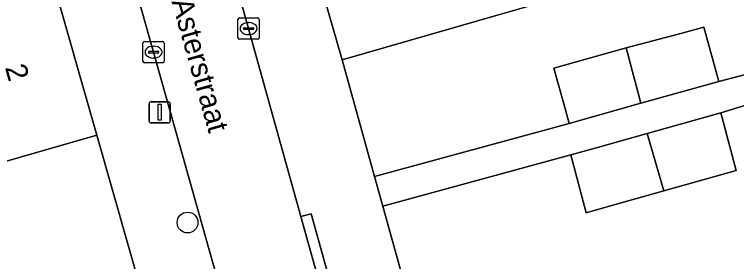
# Model space of a CAD drawing. Extents: x 161838 to 162344, y 381620 to 382160.
# Drawn here: x 162205.58 to 162239.49, y 381666.61 to 381678.21 of the extents above; entities that cross this region are included whole.
import ezdxf

# ---------------------------------------------------------------- set-up
doc = ezdxf.new("R2010")
doc.units = 0
for name, color, linetype in [('IMGEO_Boom', 7, 'Continuous'), ('IMGEO_Erf', 7, 'Continuous'), ('IMGEO_Kolk', 7, 'Continuous'), ('IMGEO_Lichtmast', 7, 'Continuous'), ('IMGEO_Muur', 7, 'Continuous'), ('IMGEO_Openbare_ruimte_label', 7, 'Continuous'), ('IMGEO_Pand', 7, 'Continuous'), ('IMGEO_Pand_nummerreeks', 7, 'Continuous'), ('IMGEO_Rijbaan_lokaal_open', 7, 'Continuous'), ('IMGEO_Voetpad_open', 7, 'Continuous')]:
    doc.layers.add(name, color=color, linetype=linetype)

msp = doc.modelspace()

# ---------------------------------------------------------------- linework, layer by layer
at = {"layer": 'IMGEO_Boom'}
msp.add_circle((162213.711, 381668.44), 0.489, dxfattribs=at)
at = {"layer": 'IMGEO_Erf'}
for points in [[(162231.383, 381679.076), (162228.305, 381678.19), (162220.972, 381676.079), (162222.493, 381670.606), (162231.635, 381673.097), (162231.456, 381673.735), (162230.91, 381675.681), (162234.306, 381676.639), (162236.809, 381677.306), (162237.954, 381677.611), (162238.666, 381675.069), (162241.528, 381675.819)], [(162169.769, 381665.971), (162175.381, 381665.835), (162175.473, 381668.458), (162179.271, 381668.325), (162182.42, 381668.215), (162182.625, 381668.207), (162183.122, 381668.19), (162183.031, 381665.574), (162201.323, 381665.149), (162201.341, 381667.859), (162205.169, 381667.776), (162205.151, 381665.056), (162211.629, 381664.907), (162209.452, 381672.542), (162204.645, 381671.168), (162202.284, 381670.493), (162200.911, 381675.128), (162199.554, 381675.698), (162198.461, 381676.191), (162196.236, 381671.255), (162193.523, 381672.479), (162190.982, 381673.625), (162193.196, 381678.533)], [(162247.052, 381676.144), (162238.757, 381673.589), (162239.475, 381670.879), (162236.071, 381669.924), (162233.575, 381669.223), (162232.433, 381668.903), (162231.714, 381671.613), (162222.883, 381669.205), (162224.963, 381661.714), (162227.769, 381662.548), (162228.727, 381659.322), (162227.16, 381658.849), (162227.713, 381657.048), (162229.234, 381657.614), (162232.618, 381658.619), (162236.003, 381659.625), (162234.51, 381664.65), (162237.36, 381665.497), (162240.211, 381666.344)]]:
    msp.add_lwpolyline(points, dxfattribs=at)
at = {"layer": 'IMGEO_Kolk'}
for p, q in [((162216.076, 381677.119), (162216.076, 381677.971)), ((162216.151, 381678.045), (162217.003, 381678.045)), ((162217.077, 381677.971), (162217.077, 381677.119)), ((162216.378, 381677.588), (162216.776, 381677.588)), ((162216.564, 381677.825), (162216.589, 381677.825)), ((162216.335, 381677.539), (162216.335, 381677.551)), ((162216.773, 381677.502), (162216.375, 381677.502)), ((162216.587, 381677.265), (162216.562, 381677.265)), ((162216.819, 381677.551), (162216.819, 381677.539)), ((162211.689, 381676.94), (162212.541, 381676.94)), ((162217.003, 381677.045), (162216.151, 381677.045)), ((162211.614, 381676.014), (162211.614, 381676.866)), ((162212.102, 381676.72), (162212.127, 381676.72)), ((162212.615, 381676.866), (162212.615, 381676.014)), ((162211.873, 381676.434), (162211.873, 381676.446)), ((162212.311, 381676.397), (162211.913, 381676.397)), ((162211.916, 381676.483), (162212.314, 381676.483)), ((162212.357, 381676.446), (162212.357, 381676.434)), ((162212.541, 381675.94), (162211.689, 381675.94)), ((162212.125, 381676.16), (162212.1, 381676.16))]:
    msp.add_line(p, q, dxfattribs=at)
for points in [[(162216.076, 381677.119), (162216.076, 381677.971)], [(162216.151, 381678.045), (162217.003, 381678.045)], [(162217.077, 381677.971), (162217.077, 381677.119)], [(162211.689, 381676.94), (162212.541, 381676.94)], [(162217.003, 381677.045), (162216.151, 381677.045)], [(162211.614, 381676.014), (162211.614, 381676.866)], [(162212.615, 381676.866), (162212.615, 381676.014)], [(162212.541, 381675.94), (162211.689, 381675.94)]]:
    msp.add_lwpolyline(points, dxfattribs=at)
for centre, radius, start, end in [((162216.153, 381677.969), 0.0765, 91.552, 178.448), ((162216.153, 381677.969), 0.0765, 91.552, 178.448), ((162217.001, 381677.969), 0.0765, 1.552, 88.448), ((162217.001, 381677.969), 0.0765, 1.552, 88.448), ((162216.375, 381677.548), 0.0403, 85.8775, 175.7526), ((162216.78, 381677.55), 0.0386, 1.7309, 96.639), ((162216.372, 381677.538), 0.0366, 178.938, 274.7102), ((162216.776, 381677.545), 0.043, 264.8664, 352.4533), ((162211.691, 381676.864), 0.0765, 91.552, 178.448), ((162211.691, 381676.864), 0.0765, 91.552, 178.448), ((162212.539, 381676.864), 0.0765, 1.552, 88.448), ((162212.539, 381676.864), 0.0765, 1.552, 88.448), ((162216.153, 381677.121), 0.0765, 181.552, 268.448), ((162216.153, 381677.121), 0.0765, 181.552, 268.448), ((162217.001, 381677.121), 0.0765, 271.552, 358.448), ((162217.001, 381677.121), 0.0765, 271.552, 358.448), ((162211.913, 381676.443), 0.0403, 85.8775, 175.7526), ((162211.91, 381676.433), 0.0366, 178.938, 274.7102), ((162212.314, 381676.44), 0.043, 264.8664, 352.4533), ((162212.318, 381676.445), 0.0386, 1.7309, 96.639), ((162211.691, 381676.016), 0.0765, 181.552, 268.448), ((162211.691, 381676.016), 0.0765, 181.552, 268.448), ((162212.539, 381676.016), 0.0765, 271.552, 358.448), ((162212.539, 381676.016), 0.0765, 271.552, 358.448)]:
    msp.add_arc(centre, radius, start, end, dxfattribs=at)
for centre, major_axis, ratio, start_param, end_param in [((162216.563, 381677.545), (-0.387, 0.002), 0.722429, 4.712389, 7.853982), ((162216.588, 381677.545), (-0.39, 0.002), 0.717154, 1.570796, 4.712389), ((162212.101, 381676.44), (-0.387, 0.002), 0.722429, 4.712389, 7.853982), ((162212.126, 381676.44), (-0.39, 0.002), 0.717154, 1.570796, 4.712389)]:
    msp.add_ellipse(centre, major_axis=major_axis, ratio=ratio, start_param=start_param, end_param=end_param, dxfattribs=at)
at = {"layer": 'IMGEO_Lichtmast'}
for p, q in [((162211.909, 381673.215), (162211.909, 381674.015)), ((162211.909, 381674.015), (162211.909, 381673.215)), ((162212.009, 381674.115), (162212.799, 381674.115)), ((162212.799, 381674.115), (162212.009, 381674.115)), ((162212.899, 381674.015), (162212.899, 381673.215)), ((162212.899, 381673.215), (162212.899, 381674.015)), ((162212.799, 381673.115), (162212.009, 381673.115)), ((162212.009, 381673.115), (162212.799, 381673.115))]:
    msp.add_line(p, q, dxfattribs=at)
msp.add_lwpolyline([(162212.329, 381673.99), (162212.479, 381673.99), (162212.479, 381673.24), (162212.329, 381673.24), (162212.329, 381673.99)], dxfattribs=at)
for centre, start, end in [((162212.009, 381674.015), 90, 180), ((162212.009, 381674.015), 90, 180), ((162212.799, 381674.015), 0, 90), ((162212.799, 381674.015), 360, 90), ((162212.009, 381673.215), 180, 270), ((162212.009, 381673.215), 180, 270), ((162212.799, 381673.215), 270, 0), ((162212.799, 381673.215), 270, 0)]:
    msp.add_arc(centre, 0.1, start, end, dxfattribs=at)
at = {"layer": 'IMGEO_Muur'}
for points in [[(162211.629, 381664.907), (162209.452, 381672.542)], [(162224.963, 381661.714), (162222.822, 381669.423)]]:
    msp.add_lwpolyline(points, dxfattribs=at)
at = {"layer": 'IMGEO_Pand'}
for points in [[(162227.057, 381682.528), (162226.929, 381682.972), (162218.956, 381683.081), (162220.972, 381676.079), (162228.305, 381678.19), (162231.383, 381679.076)], [(162203.869, 381681.706), (162201.019, 381675.369), (162200.911, 381675.128), (162202.284, 381670.493), (162204.645, 381671.168), (162209.452, 381672.542), (162207.271, 381680.172)], [(162236.809, 381677.306), (162234.306, 381676.639), (162234.998, 381674.04), (162238.666, 381675.069), (162237.954, 381677.611)], [(162234.306, 381676.639), (162230.91, 381675.681), (162231.456, 381673.735), (162231.635, 381673.097), (162234.998, 381674.04)], [(162238.757, 381673.589), (162235.287, 381672.616), (162236.071, 381669.924), (162239.475, 381670.879)], [(162235.287, 381672.616), (162232.849, 381671.932), (162231.714, 381671.613), (162232.433, 381668.903), (162233.575, 381669.223), (162236.071, 381669.924)]]:
    msp.add_lwpolyline(points, close=True, dxfattribs=at)
at = {"layer": 'IMGEO_Rijbaan_lokaal_open'}
msp.add_lwpolyline([(162220.082, 381664.97), (162219.035, 381668.723), (162215.556, 381681.205), (162213.362, 381680.611), (162211.114, 381680.002), (162216.148, 381662.111), (162217.172, 381658.471), (162217.261, 381658.154), (162220.068, 381648.178), (162220.275, 381647.442), (162224.618, 381648.697), (162222.781, 381655.288), (162220.253, 381664.356)], close=True, dxfattribs=at)
at = {"layer": 'IMGEO_Voetpad_open'}
for points in [[(162226.219, 381656.642), (162226.528, 381656.733), (162224.963, 381661.714), (162222.883, 381669.205), (162222.822, 381669.423), (162222.493, 381670.606), (162220.972, 381676.079), (162218.956, 381683.081), (162218.778, 381683.698), (162214.952, 381683.529), (162215.194, 381682.6), (162215.556, 381681.205), (162219.035, 381668.723), (162219.516, 381668.857), (162220.554, 381665.134), (162220.082, 381664.97), (162220.253, 381664.356)], [(162211.114, 381680.002), (162210.606, 381681.194), (162210.191, 381682.169), (162207.271, 381680.172), (162209.452, 381672.542), (162211.629, 381664.907), (162211.928, 381663.857), (162212.079, 381663.327), (162213.638, 381657.855), (162216.887, 381646.538), (162220.275, 381647.442), (162220.068, 381648.178)], [(162216.309, 381656.315), (162216.716, 381656.937), (162217.261, 381658.154), (162217.172, 381658.471), (162216.691, 381658.336), (162215.667, 381661.976), (162216.148, 381662.111), (162211.114, 381680.002)], [(162241.528, 381675.819), (162238.666, 381675.069), (162234.998, 381674.04), (162231.635, 381673.097), (162222.493, 381670.606), (162222.822, 381669.423), (162222.883, 381669.205), (162231.714, 381671.613), (162232.849, 381671.932), (162235.287, 381672.616), (162238.757, 381673.589), (162247.052, 381676.144)]]:
    msp.add_lwpolyline(points, dxfattribs=at)
msp.add_lwpolyline([(162220.082, 381664.97), (162220.554, 381665.134), (162219.516, 381668.857), (162219.035, 381668.723)], close=True, dxfattribs=at)

# ---------------------------------------------------------------- texts
at = {"layer": 'IMGEO_Openbare_ruimte_label'}
msp.add_text('Asterstraat', height=1, rotation=285.7879, dxfattribs=at).set_placement((162212.955, 381678.82))
at = {"layer": 'IMGEO_Pand_nummerreeks'}
msp.add_text('2', height=1, rotation=285.9523, dxfattribs=at).set_placement((162205.131, 381675.722))

doc.saveas('drawing.dxf')
